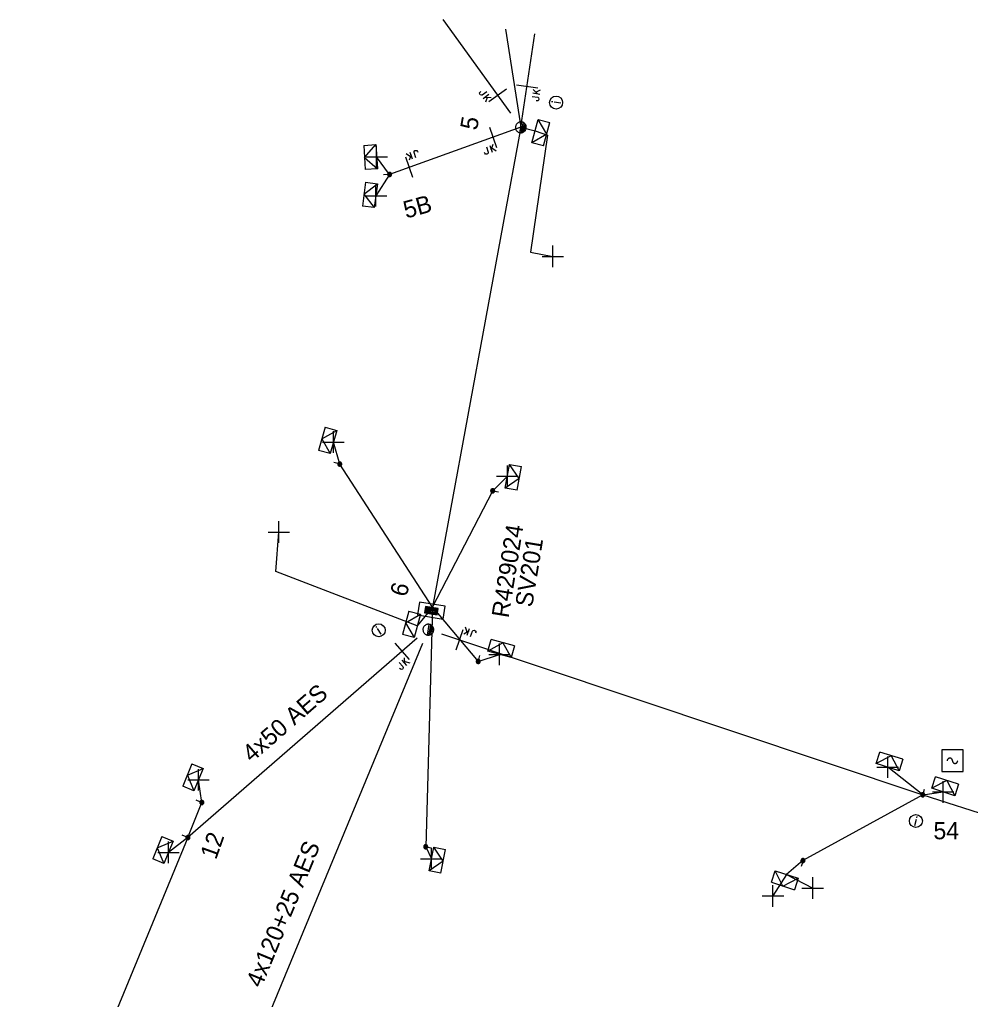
# Model space of a CAD drawing. Extents: x -540247 to -537390, y -1183887 to -1180355.
# Drawn here: x -537718.5 to -537663.5, y -1180496.1 to -1180439.4 of the extents above; entities that cross this region are included whole.
import ezdxf

# ---------------------------------------------------------------- set-up
doc = ezdxf.new("R2010")
doc.units = 0
for name, color, linetype in [('Vrstva 1', 7, 'Continuous'), ('Vrstva 10', 7, 'Continuous'), ('Vrstva 13', 7, 'Continuous'), ('Vrstva 14', 7, 'Continuous'), ('Vrstva 15', 7, 'Continuous'), ('Vrstva 18', 7, 'Continuous'), ('Vrstva 2', 7, 'Continuous'), ('Vrstva 28', 7, 'Continuous'), ('Vrstva 29', 7, 'Continuous'), ('Vrstva 30', 7, 'Continuous'), ('Vrstva 31', 7, 'Continuous'), ('Vrstva 34', 7, 'Continuous'), ('Vrstva 36', 7, 'Continuous'), ('Vrstva 50', 7, 'Continuous'), ('Vrstva 51', 7, 'Continuous'), ('Vrstva 52', 7, 'Continuous'), ('Vrstva 54', 7, 'Continuous'), ('Vrstva 59', 7, 'Continuous'), ('Vrstva 8', 7, 'Continuous'), ('Vrstva 9', 7, 'Continuous')]:
    doc.layers.add(name, color=color, linetype=linetype)

# ---------------------------------------------------------------- blocks, each defined once
blk = doc.blocks.new('NN440')
at = {"layer": 'Vrstva 2'}
for points in [[(0.63, 0), (0.63, 0.06), (0.62, 0.13), (0.6, 0.19), (0.58, 0.25), (0.55, 0.31), (0.51, 0.37), (0.47, 0.42), (0.42, 0.46), (0.37, 0.51), (0.32, 0.54), (0.26, 0.57), (0.2, 0.59), (0.13, 0.61), (0.07, 0.62), (0, 0.63), (-0.06, 0.62), (-0.13, 0.61), (-0.19, 0.59), (-0.26, 0.57), (-0.31, 0.54), (-0.37, 0.51), (-0.42, 0.46), (-0.47, 0.42), (-0.51, 0.37), (-0.54, 0.31), (-0.57, 0.25), (-0.6, 0.19), (-0.62, 0.13), (-0.63, 0.06), (-0.63, 0), (-0.63, -0.07), (-0.62, -0.14), (-0.6, -0.2), (-0.57, -0.26), (-0.54, -0.32), (-0.51, -0.37), (-0.47, -0.43), (-0.42, -0.47), (-0.37, -0.51), (-0.31, -0.55), (-0.26, -0.58), (-0.19, -0.6), (-0.13, -0.62), (-0.06, -0.63), (0, -0.63), (0.07, -0.63), (0.13, -0.62), (0.2, -0.6), (0.26, -0.58), (0.32, -0.55), (0.37, -0.51), (0.42, -0.47), (0.47, -0.43), (0.51, -0.37), (0.55, -0.32), (0.58, -0.26), (0.6, -0.2), (0.62, -0.14), (0.63, -0.07), (0.63, 0)], [(-0.63, 0), (0.63, 0)], [(-0.6, -0.18), (0.57, -0.18)], [(-0.51, -0.32), (0.5, -0.32)], [(-0.37, -0.47), (0.35, -0.47)]]:
    blk.add_lwpolyline(points, dxfattribs=at)
blk = doc.blocks.new('NN840')
at = {"layer": 'Vrstva 15'}
for points in [[(0.003, 0.619), (0.003, -0.631)], [(-0.538, -0.385), (-0.538, -0.71)], [(-0.332, -0.385), (-0.332, -0.798)], [(-0.332, -0.641), (-0.125, -0.385)], [(-0.263, -0.557), (-0.091, -0.798)], [(-0.745, -0.71), (-0.745, -0.66)], [(-0.73, -0.764), (-0.745, -0.71)], [(-0.657, -0.798), (-0.73, -0.764)], [(-0.627, -0.798), (-0.657, -0.798)], [(-0.558, -0.764), (-0.627, -0.798)], [(-0.538, -0.71), (-0.558, -0.764)]]:
    blk.add_lwpolyline(points, dxfattribs=at)
blk = doc.blocks.new('NN770')
at = {"layer": 'Vrstva 10'}
for p, q in [((0.002, 0.187), (0.002, 0.263)), ((0.002, -0.276), (0.002, 0.111))]:
    blk.add_line(p, q, dxfattribs=at)
blk.add_circle((0, -0.008), 0.375, dxfattribs=at)
blk = doc.blocks.new('NN800')
at = {"layer": 'Vrstva 1'}
for points in [[(-0.442, 0.442), (0.442, -0.442)], [(-0.442, -0.442), (0.442, 0.442)]]:
    blk.add_lwpolyline(points, dxfattribs=at)
blk = doc.blocks.new('NN620')
at = {"layer": 'Vrstva 8'}
for points in [[(0.752, 0.004), (-0.748, 0.004)], [(-0.748, 0.004), (-0.748, -0.746)], [(0.752, -0.746), (0.752, 0.004)], [(0.368, -0.18), (-0.376, -0.18)], [(-0.376, -0.18), (-0.376, -0.558)], [(-0.376, -0.558), (0.368, -0.558)], [(0.321, -0.227), (-0.329, -0.227)], [(-0.329, -0.227), (-0.329, -0.51)], [(-0.329, -0.51), (0.321, -0.51)], [(0.274, -0.274), (-0.281, -0.274)], [(-0.281, -0.274), (-0.281, -0.463)], [(-0.281, -0.463), (0.274, -0.463)], [(0.227, -0.321), (-0.234, -0.321)], [(-0.234, -0.321), (-0.234, -0.416)], [(-0.234, -0.416), (0.227, -0.416)], [(-0.193, -0.369), (0.185, -0.369)], [(0.227, -0.416), (0.227, -0.321)], [(0.274, -0.463), (0.274, -0.274)], [(0.321, -0.51), (0.321, -0.227)], [(0.368, -0.558), (0.368, -0.18)], [(-0.748, -0.746), (0.752, -0.746)]]:
    blk.add_lwpolyline(points, dxfattribs=at)
blk = doc.blocks.new('NN630')
at = {"layer": 'Vrstva 9'}
for points in [[(-0.003, -0.7), (-0.703, 0)], [(-0.703, -0.7), (-0.703, 0), (0.697, 0), (0.697, -0.7)], [(-0.003, -0.7), (0.697, 0)], [(-0.703, -0.7), (0.697, -0.7)]]:
    blk.add_lwpolyline(points, dxfattribs=at)
blk = doc.blocks.new('NN740')
at = {"layer": 'Vrstva 1'}
for points in [[(0.624, 0.624), (-0.626, 0.624)], [(-0.626, 0.624), (-0.626, -0.626)], [(0.624, -0.626), (0.624, 0.624)], [(-0.001, -0.001), (-0.002, 0.015), (-0.004, 0.031), (-0.008, 0.046), (-0.014, 0.061), (-0.021, 0.075), (-0.03, 0.089), (-0.04, 0.101), (-0.051, 0.112), (-0.063, 0.123), (-0.077, 0.131), (-0.091, 0.139), (-0.106, 0.145), (-0.121, 0.149), (-0.137, 0.151), (-0.153, 0.152), (-0.169, 0.151), (-0.185, 0.149), (-0.2, 0.145), (-0.215, 0.139), (-0.229, 0.132), (-0.243, 0.123), (-0.255, 0.113), (-0.266, 0.102), (-0.276, 0.09), (-0.285, 0.076), (-0.293, 0.062), (-0.298, 0.047), (-0.303, 0.032), (-0.305, 0.016), (-0.306, 0), (-0.306, -0.001)], [(-0.001, -0.001), (0, -0.017), (0.002, -0.032), (0.006, -0.048), (0.011, -0.062), (0.018, -0.077), (0.026, -0.09), (0.036, -0.102), (0.047, -0.114), (0.059, -0.124), (0.072, -0.133), (0.085, -0.14), (0.1, -0.146), (0.115, -0.15), (0.131, -0.153), (0.146, -0.154), (0.162, -0.154), (0.178, -0.151), (0.193, -0.148), (0.208, -0.142), (0.222, -0.135), (0.235, -0.127), (0.247, -0.118), (0.259, -0.107), (0.269, -0.095), (0.278, -0.082), (0.285, -0.068), (0.291, -0.053), (0.295, -0.038), (0.298, -0.023), (0.299, -0.007), (0.299, -0.006)], [(-0.626, -0.626), (0.624, -0.626)]]:
    blk.add_lwpolyline(points, dxfattribs=at)
blk = doc.blocks.new('NN500')
at = {"layer": 'Vrstva 2'}
for points in [[(0, -0.24), (0.02, -0.23), (0.05, -0.23), (0.07, -0.22), (0.09, -0.22), (0.12, -0.2), (0.14, -0.19), (0.16, -0.18), (0.17, -0.16), (0.19, -0.14), (0.2, -0.12), (0.21, -0.1), (0.22, -0.07), (0.23, -0.05), (0.23, -0.02), (0.23, 0), (0.23, 0.02), (0.23, 0.05), (0.22, 0.07), (0.21, 0.1), (0.2, 0.12), (0.19, 0.14), (0.17, 0.16), (0.16, 0.17), (0.14, 0.19), (0.12, 0.2), (0.09, 0.21), (0.07, 0.22), (0.05, 0.23), (0.02, 0.23), (0, 0.23), (-0.03, 0.23), (-0.05, 0.23), (-0.07, 0.22), (-0.1, 0.21), (-0.12, 0.2), (-0.14, 0.19), (-0.16, 0.17), (-0.18, 0.16), (-0.19, 0.14), (-0.2, 0.12), (-0.22, 0.1), (-0.22, 0.07), (-0.23, 0.05), (-0.23, 0.02), (-0.24, 0), (-0.23, -0.02), (-0.23, -0.05), (-0.22, -0.07), (-0.22, -0.1), (-0.2, -0.12), (-0.19, -0.14), (-0.18, -0.16), (-0.16, -0.18), (-0.14, -0.19), (-0.12, -0.2), (-0.1, -0.22), (-0.07, -0.22), (-0.05, -0.23), (-0.03, -0.23), (0, -0.24)], [(0, -0.24), (0.02, -0.23), (0.05, -0.23), (0.07, -0.22), (0.09, -0.22), (0.12, -0.2), (0.14, -0.19), (0.16, -0.18), (0.17, -0.16), (0.19, -0.14), (0.2, -0.12), (0.21, -0.1), (0.22, -0.07), (0.23, -0.05), (0.23, -0.02), (0.23, 0), (0.23, 0.02), (0.23, 0.05), (0.22, 0.07), (0.21, 0.1), (0.2, 0.12), (0.19, 0.14), (0.17, 0.16), (0.16, 0.17), (0.14, 0.19), (0.12, 0.2), (0.09, 0.21), (0.07, 0.22), (0.05, 0.23), (0.02, 0.23), (0, 0.23), (-0.03, 0.23), (-0.05, 0.23), (-0.07, 0.22), (-0.1, 0.21), (-0.12, 0.2), (-0.14, 0.19), (-0.16, 0.17), (-0.18, 0.16), (-0.19, 0.14), (-0.2, 0.12), (-0.22, 0.1), (-0.22, 0.07), (-0.23, 0.05), (-0.23, 0.02), (-0.24, 0), (-0.23, -0.02), (-0.23, -0.05), (-0.22, -0.07), (-0.22, -0.1), (-0.2, -0.12), (-0.19, -0.14), (-0.18, -0.16), (-0.16, -0.18), (-0.14, -0.19), (-0.12, -0.2), (-0.1, -0.22), (-0.07, -0.22), (-0.05, -0.23), (-0.03, -0.23), (0, -0.24)], [(0, -0.21), (0.02, -0.2), (0.04, -0.2), (0.06, -0.2), (0.08, -0.19), (0.1, -0.18), (0.12, -0.17), (0.14, -0.15), (0.15, -0.14), (0.16, -0.12), (0.18, -0.1), (0.19, -0.08), (0.19, -0.06), (0.2, -0.04), (0.2, -0.02), (0.2, 0), (0.2, 0.02), (0.2, 0.04), (0.19, 0.06), (0.19, 0.08), (0.18, 0.1), (0.16, 0.12), (0.15, 0.14), (0.14, 0.15), (0.12, 0.17), (0.1, 0.18), (0.08, 0.19), (0.06, 0.19), (0.04, 0.2), (0.02, 0.2), (0, 0.2), (-0.02, 0.2), (-0.04, 0.2), (-0.06, 0.19), (-0.08, 0.19), (-0.1, 0.18), (-0.12, 0.17), (-0.14, 0.15), (-0.15, 0.14), (-0.17, 0.12), (-0.18, 0.1), (-0.19, 0.08), (-0.2, 0.06), (-0.2, 0.04), (-0.21, 0.02), (-0.21, 0), (-0.21, -0.02), (-0.2, -0.04), (-0.2, -0.06), (-0.19, -0.08), (-0.18, -0.1), (-0.17, -0.12), (-0.15, -0.14), (-0.14, -0.15), (-0.12, -0.17), (-0.1, -0.18), (-0.08, -0.19), (-0.06, -0.2), (-0.04, -0.2), (-0.02, -0.2), (0, -0.21)], [(0, -0.18), (0.02, -0.18), (0.04, -0.17), (0.05, -0.17), (0.07, -0.16), (0.09, -0.15), (0.1, -0.14), (0.12, -0.13), (0.13, -0.12), (0.14, -0.1), (0.15, -0.09), (0.16, -0.07), (0.17, -0.05), (0.17, -0.04), (0.17, -0.02), (0.17, 0), (0.17, 0.02), (0.17, 0.04), (0.17, 0.05), (0.16, 0.07), (0.15, 0.09), (0.14, 0.1), (0.13, 0.12), (0.12, 0.13), (0.1, 0.14), (0.09, 0.15), (0.07, 0.16), (0.05, 0.17), (0.04, 0.17), (0.02, 0.17), (0, 0.18), (-0.02, 0.17), (-0.04, 0.17), (-0.06, 0.17), (-0.07, 0.16), (-0.09, 0.15), (-0.1, 0.14), (-0.12, 0.13), (-0.13, 0.12), (-0.14, 0.1), (-0.15, 0.09), (-0.16, 0.07), (-0.17, 0.05), (-0.17, 0.04), (-0.18, 0.02), (-0.18, 0), (-0.18, -0.02), (-0.17, -0.04), (-0.17, -0.05), (-0.16, -0.07), (-0.15, -0.09), (-0.14, -0.1), (-0.13, -0.12), (-0.12, -0.13), (-0.1, -0.14), (-0.09, -0.15), (-0.07, -0.16), (-0.06, -0.17), (-0.04, -0.17), (-0.02, -0.18), (0, -0.18)], [(0, -0.15), (0.01, -0.15), (0.03, -0.14), (0.04, -0.14), (0.06, -0.13), (0.07, -0.13), (0.08, -0.12), (0.1, -0.11), (0.11, -0.1), (0.12, -0.09), (0.13, -0.07), (0.13, -0.06), (0.14, -0.05), (0.14, -0.03), (0.14, -0.02), (0.14, 0), (0.14, 0.01), (0.14, 0.03), (0.14, 0.04), (0.13, 0.06), (0.13, 0.07), (0.12, 0.09), (0.11, 0.1), (0.1, 0.11), (0.08, 0.12), (0.07, 0.13), (0.06, 0.13), (0.04, 0.14), (0.03, 0.14), (0.01, 0.14), (0, 0.15), (-0.02, 0.14), (-0.03, 0.14), (-0.05, 0.14), (-0.06, 0.13), (-0.07, 0.13), (-0.09, 0.12), (-0.1, 0.11), (-0.11, 0.1), (-0.12, 0.09), (-0.13, 0.07), (-0.13, 0.06), (-0.14, 0.04), (-0.14, 0.03), (-0.15, 0.01), (-0.15, 0), (-0.15, -0.02), (-0.14, -0.03), (-0.14, -0.05), (-0.13, -0.06), (-0.13, -0.07), (-0.12, -0.09), (-0.11, -0.1), (-0.1, -0.11), (-0.09, -0.12), (-0.07, -0.13), (-0.06, -0.13), (-0.05, -0.14), (-0.03, -0.14), (-0.02, -0.15), (0, -0.15)], [(0, -0.12), (0.01, -0.12), (0.02, -0.11), (0.03, -0.11), (0.05, -0.11), (0.06, -0.1), (0.07, -0.09), (0.08, -0.09), (0.09, -0.08), (0.09, -0.07), (0.1, -0.06), (0.11, -0.05), (0.11, -0.04), (0.11, -0.02), (0.11, -0.01), (0.12, 0), (0.11, 0.01), (0.11, 0.02), (0.11, 0.04), (0.11, 0.05), (0.1, 0.06), (0.09, 0.07), (0.09, 0.08), (0.08, 0.09), (0.07, 0.09), (0.06, 0.1), (0.05, 0.11), (0.03, 0.11), (0.02, 0.11), (0.01, 0.12), (0, 0.12), (-0.01, 0.12), (-0.03, 0.11), (-0.04, 0.11), (-0.05, 0.11), (-0.06, 0.1), (-0.07, 0.09), (-0.08, 0.09), (-0.09, 0.08), (-0.1, 0.07), (-0.1, 0.06), (-0.11, 0.05), (-0.11, 0.04), (-0.12, 0.02), (-0.12, 0.01), (-0.12, 0), (-0.12, -0.01), (-0.12, -0.02), (-0.11, -0.04), (-0.11, -0.05), (-0.1, -0.06), (-0.1, -0.07), (-0.09, -0.08), (-0.08, -0.09), (-0.07, -0.09), (-0.06, -0.1), (-0.05, -0.11), (-0.04, -0.11), (-0.03, -0.11), (-0.01, -0.12), (0, -0.12)], [(0, -0.09), (0.01, -0.09), (0.02, -0.09), (0.03, -0.08), (0.03, -0.08), (0.04, -0.08), (0.05, -0.07), (0.06, -0.07), (0.06, -0.06), (0.07, -0.05), (0.07, -0.04), (0.08, -0.04), (0.08, -0.03), (0.08, -0.02), (0.09, -0.01), (0.09, 0), (0.09, 0.01), (0.08, 0.02), (0.08, 0.03), (0.08, 0.03), (0.07, 0.04), (0.07, 0.05), (0.06, 0.06), (0.06, 0.06), (0.05, 0.07), (0.04, 0.07), (0.03, 0.08), (0.03, 0.08), (0.02, 0.08), (0.01, 0.09), (0, 0.09), (-0.01, 0.09), (-0.02, 0.08), (-0.03, 0.08), (-0.04, 0.08), (-0.04, 0.07), (-0.05, 0.07), (-0.06, 0.06), (-0.07, 0.06), (-0.07, 0.05), (-0.08, 0.04), (-0.08, 0.03), (-0.08, 0.03), (-0.09, 0.02), (-0.09, 0.01), (-0.09, 0), (-0.09, -0.01), (-0.09, -0.02), (-0.08, -0.03), (-0.08, -0.04), (-0.08, -0.04), (-0.07, -0.05), (-0.07, -0.06), (-0.06, -0.07), (-0.05, -0.07), (-0.04, -0.08), (-0.04, -0.08), (-0.03, -0.08), (-0.02, -0.09), (-0.01, -0.09), (0, -0.09)], [(0, -0.06), (0, -0.06), (0.01, -0.06), (0.02, -0.05), (0.02, -0.05), (0.03, -0.05), (0.03, -0.05), (0.04, -0.04), (0.04, -0.04), (0.05, -0.03), (0.05, -0.03), (0.05, -0.02), (0.05, -0.02), (0.05, -0.01), (0.06, -0.01), (0.06, 0), (0.06, 0.01), (0.05, 0.01), (0.05, 0.02), (0.05, 0.02), (0.05, 0.03), (0.05, 0.03), (0.04, 0.04), (0.04, 0.04), (0.03, 0.05), (0.03, 0.05), (0.02, 0.05), (0.02, 0.05), (0.01, 0.06), (0, 0.06), (0, 0.06), (-0.01, 0.06), (-0.01, 0.06), (-0.02, 0.05), (-0.02, 0.05), (-0.03, 0.05), (-0.03, 0.05), (-0.04, 0.04), (-0.04, 0.04), (-0.05, 0.03), (-0.05, 0.03), (-0.05, 0.02), (-0.06, 0.02), (-0.06, 0.01), (-0.06, 0.01), (-0.06, 0), (-0.06, -0.01), (-0.06, -0.01), (-0.06, -0.02), (-0.05, -0.02), (-0.05, -0.03), (-0.05, -0.03), (-0.04, -0.04), (-0.04, -0.04), (-0.03, -0.05), (-0.03, -0.05), (-0.02, -0.05), (-0.02, -0.05), (-0.01, -0.06), (-0.01, -0.06), (0, -0.06)], [(0, -0.03), (0, -0.03), (0, -0.03), (0.01, -0.03), (0.01, -0.03), (0.01, -0.02), (0.02, -0.02), (0.02, -0.02), (0.02, -0.02), (0.02, -0.02), (0.02, -0.01), (0.02, -0.01), (0.03, -0.01), (0.03, -0.01), (0.03, 0), (0.03, 0), (0.03, 0), (0.03, 0.01), (0.03, 0.01), (0.02, 0.01), (0.02, 0.01), (0.02, 0.02), (0.02, 0.02), (0.02, 0.02), (0.02, 0.02), (0.01, 0.02), (0.01, 0.02), (0.01, 0.03), (0, 0.03), (0, 0.03), (0, 0.03), (0, 0.03), (-0.01, 0.03), (-0.01, 0.03), (-0.01, 0.02), (-0.02, 0.02), (-0.02, 0.02), (-0.02, 0.02), (-0.02, 0.02), (-0.02, 0.02), (-0.03, 0.01), (-0.03, 0.01), (-0.03, 0.01), (-0.03, 0.01), (-0.03, 0), (-0.03, 0), (-0.03, 0), (-0.03, -0.01), (-0.03, -0.01), (-0.03, -0.01), (-0.03, -0.01), (-0.02, -0.02), (-0.02, -0.02), (-0.02, -0.02), (-0.02, -0.02), (-0.02, -0.02), (-0.01, -0.03), (-0.01, -0.03), (-0.01, -0.03), (0, -0.03), (0, -0.03)], [(0.23, 0), (0.7, 0)]]:
    blk.add_lwpolyline(points, dxfattribs=at)

msp = doc.modelspace()

# ---------------------------------------------------------------- linework, layer by layer
at = {"layer": 'Vrstva 50'}
for points in [[(-537694.018, -1180439.412), (-537690.098, -1180444.825)], [(-537690.386, -1180439.973), (-537689.5, -1180445.65)], [(-537689.5, -1180445.65), (-537688.69, -1180440.235)], [(-537689.5, -1180445.65), (-537697.101, -1180448.375)], [(-537689.5, -1180445.65), (-537694.626, -1180473.441)], [(-537695.509, -1180475.222), (-537708.786, -1180486.772), (-537714.289, -1180500.117), (-537718.536, -1180510.223)], [(-537694.091, -1180474.974), (-537666.22, -1180484.298), (-537653.537, -1180488.361)], [(-537706.255, -1180502.27), (-537705.642, -1180500.791), (-537695.184, -1180475.522)]]:
    msp.add_lwpolyline(points, dxfattribs=at)
at = {"layer": 'Vrstva 52'}
for points in [[(-537689.5, -1180445.65), (-537688.678, -1180445.861), (-537687.947, -1180446.103), (-537688.937, -1180452.883), (-537687.646, -1180453.125)], [(-537694.626, -1180473.442), (-537695.499, -1180474.516), (-537703.695, -1180471.37), (-537703.52, -1180469.088)]]:
    msp.add_lwpolyline(points, dxfattribs=at)
at = {"layer": 'Vrstva 54'}
for points in [[(-537697.101, -1180448.375), (-537697.894, -1180449.611)], [(-537666.22, -1180484.298), (-537668.25, -1180482.701)], [(-537708.786, -1180486.772), (-537707.981, -1180484.744), (-537708.174, -1180483.433)], [(-537666.22, -1180484.298), (-537673.156, -1180488.108), (-537674.103, -1180488.915)], [(-537666.22, -1180484.298), (-537665.037, -1180484.134)], [(-537708.786, -1180486.772), (-537709.912, -1180487.635)]]:
    msp.add_lwpolyline(points, dxfattribs=at)
at = {"layer": 'Vrstva 59'}
for points in [[(-537674.103, -1180488.915), (-537674.894, -1180490.154)], [(-537674.103, -1180488.915), (-537672.59, -1180489.702)]]:
    msp.add_lwpolyline(points, dxfattribs=at)
at = {"layer": 'Vrstva 8'}
for points in [[(-537697.101, -1180448.375), (-537697.858, -1180447.352)], [(-537694.626, -1180473.442), (-537699.992, -1180465.146), (-537700.356, -1180463.875)], [(-537694.626, -1180473.442), (-537691.131, -1180466.698), (-537690.276, -1180465.852)], [(-537694.626, -1180473.441), (-537695.011, -1180487.305), (-537694.68, -1180488.008)], [(-537694.626, -1180473.442), (-537691.967, -1180476.575), (-537690.737, -1180476.171)]]:
    msp.add_lwpolyline(points, dxfattribs=at)

# ---------------------------------------------------------------- block references
at = {"layer": 'Vrstva 13'}
for name, p, xscale, yscale, rotation in [('NN440', (-537689.499, -1180445.65), 0.5, 0.5, 79.54707228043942), ('NN500', (-537697.101, -1180448.375), 0.5, 0.5, -176.22699987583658), ('NN500', (-537699.992, -1180465.146), 0.5000000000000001, 0.5, 164.08400002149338), ('NN500', (-537691.131, -1180466.698), 0.49999999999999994, 0.49999999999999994, -10.230999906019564), ('NN440', (-537694.86, -1180474.74), 0.5, 0.5, 79.7180916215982), ('NN500', (-537691.967, -1180476.575), 0.5, 0.5000000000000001, 74.88299995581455), ('NN500', (-537666.22, -1180484.298), 0.5, 0.5, 72.01400000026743), ('NN500', (-537707.981, -1180484.744), 0.5, 0.5, 157.366999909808), ('NN500', (-537708.786, -1180486.772), 0.5, 0.49999999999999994, 157.6050000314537), ('NN500', (-537695.011, -1180487.305), 0.49999999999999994, 0.5, -11.138000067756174), ('NN500', (-537673.156, -1180488.108), 0.5, 0.5, -107.860000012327)]:
    msp.add_blockref(name, p, dxfattribs=dict(at, xscale=xscale, yscale=yscale, rotation=rotation))
at = {"layer": 'Vrstva 18'}
for p, rotation in [((-537690.84, -1180443.801), -54.08484726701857), ((-537689.145, -1180443.276), 81.4932083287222), ((-537691.118, -1180446.23), 19.723033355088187), ((-537695.955, -1180447.964), -160.27696666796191), ((-537693.04, -1180475.325), 161.5027834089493), ((-537696.391, -1180475.989), 41.02083606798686)]:
    msp.add_blockref('NN840', p, dxfattribs=dict(at, rotation=rotation))
at = {"layer": 'Vrstva 28', "rotation": 170.80000006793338}
msp.add_blockref('NN620', (-537694.74, -1180474), dxfattribs=at)
at = {"layer": 'Vrstva 31'}
for p, rotation in [((-537688.678, -1180445.861), 74.89890277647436), ((-537697.858, -1180447.353), -86.2267555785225), ((-537697.894, -1180449.611), -97.64768337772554), ((-537700.356, -1180463.875), -105.91583056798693), ((-537690.276, -1180465.852), 79.76937495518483), ((-537695.499, -1180474.516), -104.73012228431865), ((-537690.737, -1180476.171), 164.8828333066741), ((-537668.25, -1180482.701), 162.71729445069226), ((-537708.174, -1180483.433), -112.63329166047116), ((-537665.037, -1180484.134), 162.01426116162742), ((-537709.912, -1180487.635), -112.39539719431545), ((-537694.68, -1180488.008), 78.86212778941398), ((-537674.103, -1180488.915), -17.860094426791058)]:
    msp.add_blockref('NN630', p, dxfattribs=dict(at, rotation=rotation))
at = {"layer": 'Vrstva 34'}
for p, rotation in [((-537697.858, -1180447.352), 45.00000009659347), ((-537697.894, -1180449.611), 45), ((-537687.646, -1180453.125), 44.99999995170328), ((-537700.356, -1180463.875), 45), ((-537690.276, -1180465.852), 45.000000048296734), ((-537703.52, -1180469.088), 45), ((-537690.737, -1180476.171), 45), ((-537668.25, -1180482.701), 45), ((-537708.174, -1180483.433), 45), ((-537665.037, -1180484.133), 45), ((-537709.912, -1180487.634), 45), ((-537694.68, -1180488.008), 45), ((-537674.894, -1180490.154), 45), ((-537672.59, -1180489.702), 45)]:
    msp.add_blockref('NN800', p, dxfattribs=dict(at, rotation=rotation))
msp.add_blockref('NN740', (-537664.494, -1180482.328), dxfattribs=at)
at = {"layer": 'Vrstva 36'}
for p, rotation in [((-537687.465, -1180444.215), 80.39479724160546), ((-537697.736, -1180474.767), 32.949213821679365), ((-537666.615, -1180485.808), -14.620875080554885)]:
    msp.add_blockref('NN770', p, dxfattribs=dict(at, rotation=rotation))

# ---------------------------------------------------------------- texts
at = {"layer": 'Vrstva 14'}
for s, rotation, p in [('5', 79.704, (-537692.042, -1180445.858)), ('5B', 15.429, (-537696.146, -1180450.939)), ('6', 75.422, (-537696.128, -1180472.882)), ('12', 70.362, (-537707.158, -1180488.095))]:
    msp.add_text(s, height=1, rotation=rotation, dxfattribs=at).set_placement(p)
msp.add_text('54', height=1, dxfattribs=at).set_placement((-537665.599, -1180486.874))
at = {"layer": 'Vrstva 29'}
msp.add_text('R429024', height=1, rotation=80.8, dxfattribs=at).set_placement((-537690.214, -1180474.095))
at = {"layer": 'Vrstva 30'}
msp.add_text('SV201', height=1, rotation=80.8, dxfattribs=at).set_placement((-537688.846, -1180473.478))
at = {"layer": 'Vrstva 51'}
for s, rotation, p in [('4x50 AES', 41.021, (-537705.088, -1180482.46)), ('4x120+25 AES', 67.517, (-537704.532, -1180495.524))]:
    msp.add_text(s, height=1, rotation=rotation, dxfattribs=at).set_placement(p)

doc.saveas('drawing.dxf')
